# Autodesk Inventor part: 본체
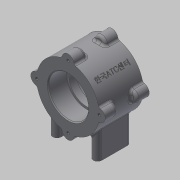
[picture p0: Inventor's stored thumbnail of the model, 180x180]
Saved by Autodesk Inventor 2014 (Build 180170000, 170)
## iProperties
Created: 2015-03
Part Number: 본체
Material: Generic
Document SubType Name: Modeling
Designer: MYHOME
Density: 1 g/cm^3
Appearance: Default
Author: MYHOME
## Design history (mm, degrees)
sketch "스케치2"
  geometry: C1 r 37 at (0, 0); 1 further point
  constraints: 1 centre point, 1 coincident
  dimensions: "d0" = 74 diameter of C1
extrude "돌출1" new body sketch "스케치2" distance "d1" = 26; taper "d2" = 0 deg
sketch "스케치3"
  geometry: C1 r 7 at (0, 37); C2 r 7 at (-37, 0); C3 r 7 at (37, 0); C4 r 7 at (0, -37); A1 r 37 centre (0, 0) between (0, 37) and (-37, 0) reference
  constraints: 4 centre point, 4 point on circle, 2 horizontal alignment, 2 vertical alignment
  dimensions: "d3" = 7 radius of C1; "d4" = 7 radius of C2; "d5" = 7 radius of C3; "d6" = 7 radius of C4
extrude "돌출2" join sketch "스케치3" distance "d7" = 15; taper "d8" = 0 deg
sketch "스케치4"
  geometry: A1 r 7 centre (37, 0) between (36.338, -6.969) and (36.338, 6.969) reference; A2 r 7 centre (0, 37) between (6.969, 36.338) and (-6.969, 36.338) reference; A3 r 7 centre (-37, 0) between (-36.338, 6.969) and (-36.338, -6.969) reference; A4 r 7 centre (0, -37) between (-6.969, -36.338) and (6.969, -36.338) reference; 4 further points
  constraints: 4 coincident
hole "구멍1" sketch "스케치4" at (0, 37), (-37, 0), (0, -37), (37, 0) diameter "d9" = 3.242; stored, may be unused: countersink angle "d13" = 90 deg, drill point angle "d15" = 118 deg; dims "d10" = 8, "d11" = 4, "d12" = 2, "d14" = 11
fillet "모깎기1" dims "d16" = 3
fillet "모깎기2" dims "d17" = 3
fillet "모깎기3" dims "d18" = 3
hole "구멍2" diameter "d21" = 42; stored, may be unused: countersink angle "d25" = 90 deg, drill point angle "d27" = 0 deg; dims "d19" = 10, "d20" = 10, "d22" = 8, "d23" = 47, "d24" = 22, "d26" = 26
chamfer "모따기1" distance "d28" = 1; stored, may be unused: second distance "d29" = 2, angle "d30" = 45 deg
fillet "모깎기4" dims "d31" = 0.3
node "작업 평면1"
sketch "스케치6"
  geometry: L1 (-24, 15)-(-24, -15); L2 (-29, 15)-(-29, -15); L3 (-19, -15)-(-19, 15); L4 (24, 15)-(24, -15); L5 (29, 15)-(29, -15); L6 (19, -15)-(19, 15); L7 (0, 0)-(0, 20); A1 r 5 centre (-24, 15) between (-19, 15) and (-29, 15); A2 r 5 centre (-24, -15) between (-29, -15) and (-19, -15); A3 r 5 centre (24, 15) between (29, 15) and (19, 15); A4 r 5 centre (24, -15) between (19, -15) and (29, -15); 2 further points
  constraints: 18 end point, 8 point on circle, 8 tangent, 4 centre point, 4 parallel, 2 horizontal alignment, 2 midpoint, 1 symmetric about line, 1 vertical
  dimensions: "d33" = 40 dimension on A3 A4; "d34" = 40 dimension on A1 A2; "d36" = 5 radius of A1; "d37" = 48 distance of L4.end L1.end; "d38" = 10 distance between parallel lines of L5 L6; "d39" = 20 distance of L7.start L7.end
extrude "돌출3" join sketch "스케치6" stored distance "d40" = 15; taper "d41" = 0 deg
sketch "스케치7"
  geometry: L1 (29, 15)-(29, -15) reference; L2 (19, -15)-(19, 15) reference; A1 r 5 centre (-24, -15) between (-29, -15) and (-19, -15) reference; A2 r 5 centre (-24, 15) between (-19, 15) and (-29, 15) reference; A3 r 5 centre (24, 15) between (29, 15) and (19, 15) reference; A4 r 5 centre (24, -15) between (19, -15) and (29, -15) reference; 5 further points
  constraints: 4 coincident
hole "구멍3" sketch "스케치7" at (-24, 15), (-24, -15), (24, -15), (24, 15) diameter "d42" = 4.134; stored, may be unused: countersink angle "d46" = 90 deg, drill point angle "d48" = 118 deg; dims "d43" = 6, "d44" = 47, "d45" = 22, "d47" = 8
fillet "모깎기5" dims "d49" = 3
sketch "스케치8"
  geometry: L1 (0, 0)-(-21, 0); L2 (0, 0)-(-26.163, 26.163); A1 r 37 centre (0, 0) between (-9.104, 35.863) and (-35.863, 9.104) reference; 1 further point
  constraints: 5 end point, 1 horizontal, 1 horizontal alignment, 1 point on circle, 1 other
  dimensions: "d51" = 45 deg angle of L2 L1
node "작업 평면3"
sketch "스케치9"
  geometry: 2 further points
  constraints: 1 coincident, 1 other
feature "엠보싱1" sketch "스케치9" dims "d53" = 0.5, "d54" = 0
node "솔리드1"
mirror "대칭1"
mirror "대칭2"
node "투영된 루프1"
other parameters: "d32" = -56
